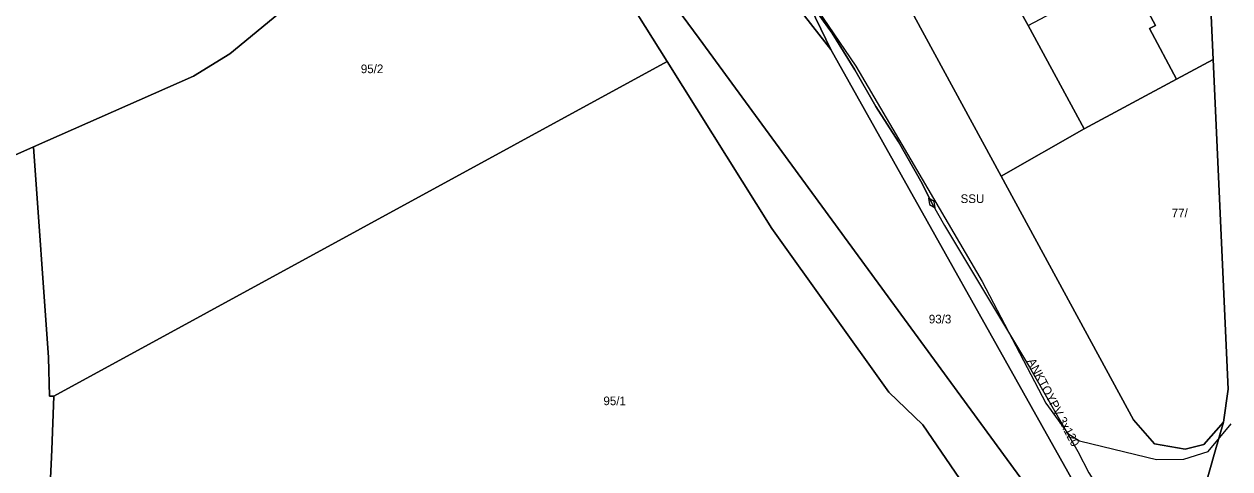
# Model space of a CAD drawing. Extents: x -793400 to -756198, y -1074141 to -1042963.
# Drawn here: x -783438.8 to -783334.3, y -1065252.1 to -1065213.5 of the extents above; entities that cross this region are included whole.
import ezdxf

# ---------------------------------------------------------------- set-up
doc = ezdxf.new("R2010")
doc.units = 0
for name, color, linetype in [('Parcela', 7, 'Continuous'), ('Popiskový text - Parcela', 7, 'Continuous'), ('Popiskový text - Spojka nn - Typ', 7, 'Continuous'), ('Popiskový text - Vedení vn kabelové', 7, 'Continuous'), ('Spojka nn', 7, 'Continuous'), ('Spojnice nn', 7, 'Continuous'), ('Spojnice vn', 7, 'Continuous'), ('Stavební objekt', 7, 'Continuous'), ('Vedení 22 kV kabelové', 7, 'Continuous'), ('Vedení nn kabelové', 7, 'Continuous')]:
    doc.layers.add(name, color=color, linetype=linetype)

msp = doc.modelspace()

# ---------------------------------------------------------------- linework, layer by layer
at = {"layer": 'Parcela'}
for points in [[(-783333.46, -1065173.04), (-783333.27, -1065184.1), (-783332.18, -1065183.83), (-783332.44, -1065204.1), (-783331.2, -1065229.69), (-783329.02, -1065234.74), (-783333.33, -1065281.22), (-783340.36, -1065267.55), (-783335.58, -1065250.68), (-783334.84, -1065248.08), (-783334.44, -1065245.21), (-783335.73, -1065216.58), (-783336.76, -1065193.79), (-783337.72, -1065163.69), (-783337.71, -1065162.3), (-783336.8, -1065155.92), (-783334.89, -1065142.75), (-783332.76, -1065128.1), (-783330.21, -1065117.78), (-783325.71, -1065116.67), (-783328.95, -1065129.54), (-783331.93, -1065148.39), (-783333.28, -1065158.38), (-783333.36, -1065165.67)], [(-783346.09, -1065256.41), (-783341.85, -1065272.8), (-783351.87, -1065253.68), (-783380.31, -1065214.76), (-783386.7, -1065206.1), (-783423.43, -1065175.81), (-783416.87, -1065167.97), (-783412.92, -1065172.99), (-783401.04, -1065184.24), (-783391.13, -1065189.93), (-783381.67, -1065199.34), (-783368.9, -1065215.74)], [(-783341.85, -1065272.8), (-783345.64, -1065275.81), (-783354.48, -1065257.7), (-783360.91, -1065248.3), (-783363.87, -1065245.46), (-783374.02, -1065231.27), (-783383.09, -1065216.77), (-783387.54, -1065209.66), (-783390.81, -1065205.75), (-783403.39, -1065195.23), (-783416.03, -1065186.09), (-783426, -1065178.89), (-783423.43, -1065175.81), (-783386.7, -1065206.1), (-783380.31, -1065214.76), (-783351.87, -1065253.68)], [(-783416.03, -1065186.09), (-783403.39, -1065195.23), (-783407.54, -1065201.94), (-783409.86, -1065205.07), (-783416.28, -1065212.21), (-783421, -1065216.11), (-783424.16, -1065218.04), (-783438.03, -1065224.17), (-783441.5, -1065225.71), (-783447.41, -1065228.37), (-783452.73, -1065215.33), (-783452.34, -1065209.47), (-783459.78, -1065208.85), (-783460.26, -1065214.69), (-783460.3, -1065215.24), (-783468.73, -1065213.48), (-783469.27, -1065213.37), (-783464.68, -1065192.93), (-783464.13, -1065193.03), (-783454.3, -1065194.92), (-783453.6, -1065190.73), (-783449.1, -1065190.18)], [(-783372.84, -1065207.51), (-783368.9, -1065215.74), (-783381.67, -1065199.34), (-783391.13, -1065189.93), (-783383.31, -1065194.42), (-783377.51, -1065197.74)], [(-783336.76, -1065193.79), (-783335.73, -1065216.58), (-783338.92, -1065218.3), (-783341.26, -1065213.91), (-783340.73, -1065213.63), (-783343.2, -1065209.05), (-783346.03, -1065210.57), (-783347.35, -1065208.17), (-783353.07, -1065211.27), (-783351.78, -1065213.65), (-783346.93, -1065222.62), (-783354.11, -1065226.72), (-783362.38, -1065211.5)], [(-783383.09, -1065216.77), (-783436.26, -1065245.82), (-783436.65, -1065245.81), (-783436.74, -1065242.46), (-783438.03, -1065224.17), (-783424.16, -1065218.04), (-783421, -1065216.11), (-783416.28, -1065212.21), (-783409.86, -1065205.07), (-783407.54, -1065201.94), (-783403.39, -1065195.23), (-783390.81, -1065205.75), (-783387.54, -1065209.66)], [(-783347.35, -1065208.17), (-783346.03, -1065210.57), (-783343.2, -1065209.05), (-783340.73, -1065213.63), (-783341.26, -1065213.91), (-783338.92, -1065218.3), (-783346.93, -1065222.62), (-783351.78, -1065213.65), (-783353.07, -1065211.27)], [(-783336.55, -1065250), (-783338.15, -1065250.41), (-783340.83, -1065249.95), (-783342.64, -1065247.88), (-783354.11, -1065226.72), (-783346.93, -1065222.62), (-783338.92, -1065218.3), (-783335.73, -1065216.58), (-783334.44, -1065245.21), (-783334.84, -1065248.08)], [(-783354.48, -1065257.7), (-783345.64, -1065275.81), (-783362.61, -1065289.16), (-783369.7, -1065292.34), (-783373.71, -1065291.76), (-783373.22, -1065280.42), (-783396.35, -1065277.34), (-783395.96, -1065274.37), (-783419.04, -1065271.36), (-783429.89, -1065269.94), (-783429.62, -1065263.22), (-783418.27, -1065264.71), (-783417.28, -1065255.88), (-783428.78, -1065254.48), (-783436.59, -1065253.58), (-783436.45, -1065250.48), (-783436.26, -1065245.82), (-783383.09, -1065216.77), (-783374.02, -1065231.27), (-783363.87, -1065245.46), (-783360.91, -1065248.3)], [(-783436.45, -1065250.48), (-783436.59, -1065253.58), (-783444.3, -1065253.99), (-783455.9, -1065253.3), (-783460.81, -1065253.03), (-783461.03, -1065253.4), (-783461.1, -1065254.06), (-783473.08, -1065253.23), (-783474.48, -1065249.17), (-783473.04, -1065235.09), (-783472.58, -1065232.29), (-783471.42, -1065231.93), (-783447.41, -1065228.37), (-783441.5, -1065225.71), (-783438.03, -1065224.17), (-783436.74, -1065242.46), (-783436.65, -1065245.81), (-783436.26, -1065245.82)]]:
    msp.add_lwpolyline(points, close=True, dxfattribs=at)
for points in [[(-783346.09, -1065256.41), (-783368.9, -1065215.74), (-783372.84, -1065207.51), (-783377.51, -1065197.74), (-783383.31, -1065194.42), (-783391.13, -1065189.93), (-783414.06, -1065167.1), (-783415.13, -1065165.88), (-783421.56, -1065158.5), (-783424.51, -1065149.24), (-783423.77, -1065139.97)], [(-783413.48, -1065139.98), (-783415.63, -1065142.9), (-783416.64, -1065146.29), (-783416.41, -1065149.77), (-783415.07, -1065153), (-783412.76, -1065155.51), (-783405.15, -1065162.67), (-783400.84, -1065166.73), (-783391.75, -1065175.3), (-783375.51, -1065193.02), (-783362.38, -1065211.5), (-783354.11, -1065226.72), (-783342.64, -1065247.88), (-783340.83, -1065249.95), (-783338.15, -1065250.41), (-783336.55, -1065250), (-783334.84, -1065248.08), (-783335.58, -1065250.68), (-783340.36, -1065267.55)]]:
    msp.add_lwpolyline(points, dxfattribs=at)
at = {"layer": 'Spojka nn'}
msp.add_lwpolyline([(-783360.43, -1065228.64), (-783360.34, -1065229.19), (-783359.85, -1065229.46), (-783359.94, -1065228.91)], close=True, dxfattribs=at)
at = {"layer": 'Spojnice nn'}
for points in [[(-783360.14, -1065229.05), (-783360.97, -1065227.35), (-783363.02, -1065223.74), (-783365, -1065220.66), (-783366.81, -1065217.49), (-783368.78, -1065214.31), (-783370.95, -1065211.27), (-783372.97, -1065208.27), (-783375.08, -1065205.29), (-783377.18, -1065202.72), (-783379.81, -1065199.33), (-783382.35, -1065196.31), (-783385.05, -1065193.35), (-783387.62, -1065190.49), (-783389.83, -1065188.1), (-783393.09, -1065184.92), (-783395.7, -1065182.16), (-783397.33, -1065180.69), (-783398.14, -1065180.01), (-783399.47, -1065179.91), (-783400.91, -1065180.45)], [(-783360.14, -1065229.05), (-783359.04, -1065230.99), (-783351.66, -1065243.31), (-783347.48, -1065250.62), (-783346.52, -1065252.46), (-783344.19, -1065256.1), (-783341.55, -1065260.45), (-783340.36, -1065266.9), (-783340.16, -1065273.63), (-783340.06, -1065281.13), (-783339.42, -1065285.78)]]:
    msp.add_lwpolyline(points, dxfattribs=at)
at = {"layer": 'Spojnice vn'}
msp.add_lwpolyline([(-783452.28, -1065183.03), (-783421.94, -1065182.22), (-783411.59, -1065181.15), (-783406.09, -1065180.81), (-783401.01, -1065180.27), (-783398.71, -1065179.69), (-783397.22, -1065180.54), (-783393.17, -1065184.74), (-783385.15, -1065192.91), (-783378.14, -1065201.41), (-783371.94, -1065209.46), (-783366.72, -1065217.17), (-783361.95, -1065225.31), (-783355.77, -1065235.87), (-783350.25, -1065246.43), (-783348.33, -1065249.06), (-783347.31, -1065249.68), (-783342.44, -1065250.87), (-783340.64, -1065251.31), (-783338.29, -1065251.28), (-783336.18, -1065250.61), (-783334.18, -1065248.21)], dxfattribs=at)
at = {"layer": 'Stavební objekt'}
msp.add_lwpolyline([(-783338.92, -1065218.3), (-783346.93, -1065222.62), (-783351.78, -1065213.65), (-783346.03, -1065210.57), (-783343.2, -1065209.05), (-783340.73, -1065213.63), (-783341.26, -1065213.91)], close=True, dxfattribs=at)
at = {"layer": 'Vedení 22 kV kabelové'}
msp.add_lwpolyline([(-783452.28, -1065183.03), (-783421.94, -1065182.22), (-783411.59, -1065181.15), (-783406.09, -1065180.81), (-783401.01, -1065180.27), (-783398.71, -1065179.69), (-783397.22, -1065180.54), (-783393.17, -1065184.74), (-783385.15, -1065192.91), (-783378.14, -1065201.41), (-783371.94, -1065209.46), (-783366.72, -1065217.17), (-783361.95, -1065225.31), (-783355.77, -1065235.87), (-783350.25, -1065246.43), (-783348.33, -1065249.06), (-783347.31, -1065249.68), (-783342.44, -1065250.87), (-783340.64, -1065251.31), (-783338.29, -1065251.28), (-783336.18, -1065250.61), (-783334.18, -1065248.21)], dxfattribs=at)
at = {"layer": 'Vedení nn kabelové'}
for points in [[(-783455.41, -1065188.99), (-783400.91, -1065180.45), (-783399.47, -1065179.91), (-783398.14, -1065180.01), (-783397.33, -1065180.69), (-783395.7, -1065182.16), (-783393.09, -1065184.92), (-783389.83, -1065188.1), (-783387.62, -1065190.49), (-783385.05, -1065193.35), (-783382.35, -1065196.31), (-783379.81, -1065199.33), (-783377.18, -1065202.72), (-783375.08, -1065205.29), (-783372.97, -1065208.27), (-783370.95, -1065211.27), (-783368.78, -1065214.31), (-783366.81, -1065217.49), (-783365, -1065220.66), (-783363.02, -1065223.74), (-783360.97, -1065227.35), (-783360.14, -1065229.05)], [(-783360.14, -1065229.05), (-783359.04, -1065230.99), (-783351.66, -1065243.31), (-783347.48, -1065250.62), (-783346.52, -1065252.46), (-783344.19, -1065256.1), (-783341.55, -1065260.45), (-783340.36, -1065266.9), (-783340.16, -1065273.63), (-783340.06, -1065281.13), (-783339.45, -1065285.58), (-783339.44, -1065286.09), (-783339.61, -1065286.09), (-783339.61, -1065285.94)]]:
    msp.add_lwpolyline(points, dxfattribs=at)

# ---------------------------------------------------------------- texts
at = {"layer": 'Popiskový text - Parcela'}
for s, p in [('95/2', (-783409.65, -1065217.78)), ('77/', (-783339.33, -1065230.29)), ('93/3', (-783360.39, -1065239.5)), ('95/1', (-783388.61, -1065246.6))]:
    msp.add_text(s, height=0.75, dxfattribs=at).set_placement(p)
at = {"layer": 'Popiskový text - Spojka nn - Typ'}
msp.add_text('SSU', height=0.75, dxfattribs=at).set_placement((-783357.64, -1065229.05))
at = {"layer": 'Popiskový text - Vedení vn kabelové'}
msp.add_text('ANKTOYPV 3x120', height=0.75, rotation=297.5943, dxfattribs=at).set_placement((-783351.88, -1065242.77))

doc.saveas('drawing.dxf')
